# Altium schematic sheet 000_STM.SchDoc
size A; SheetNumber: 2; SheetTotal: 5
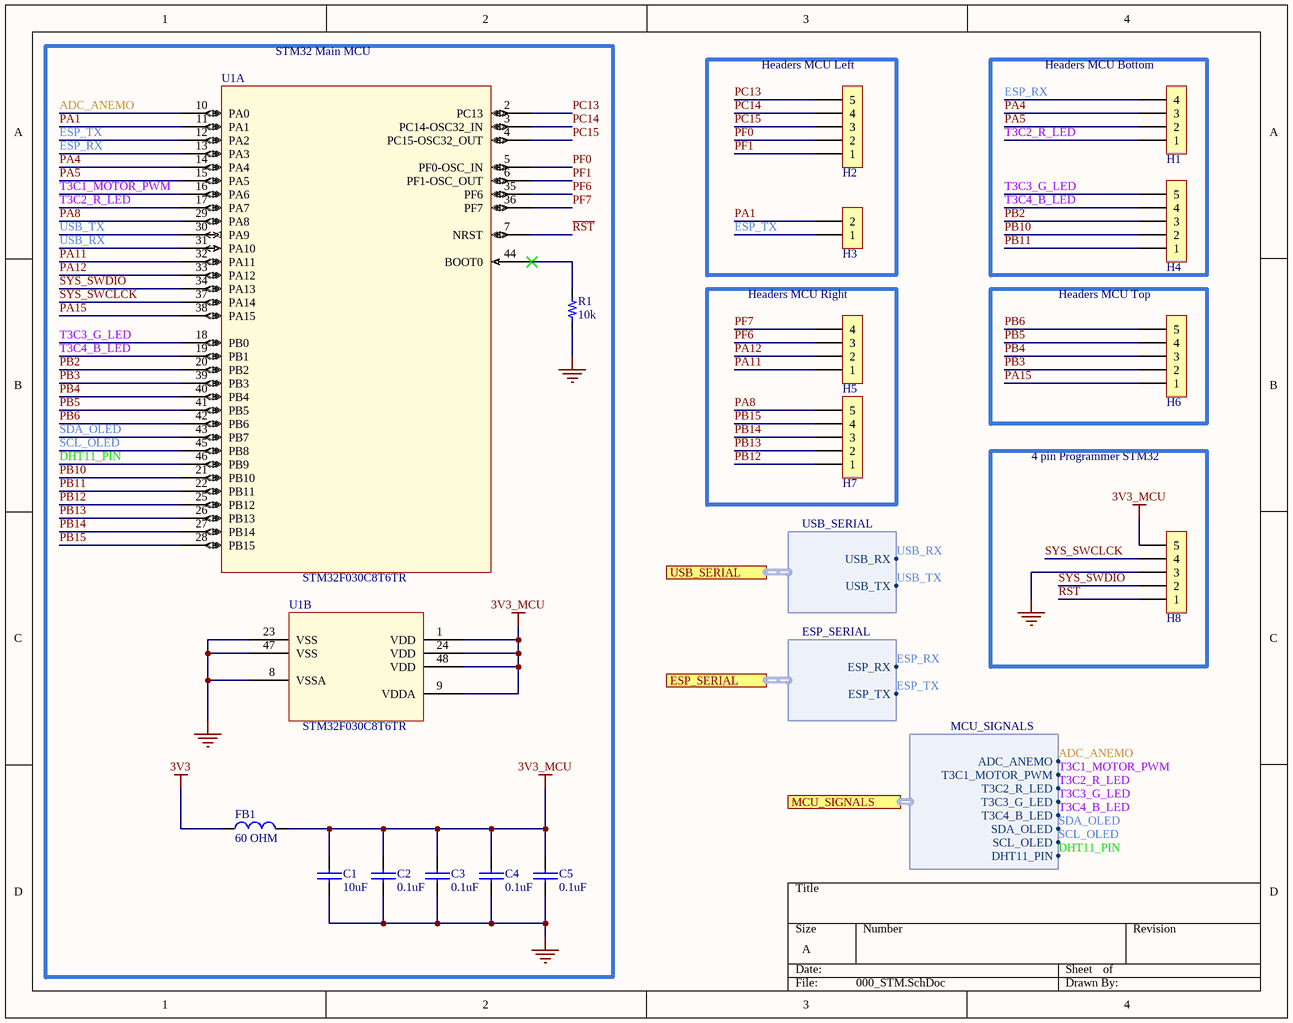
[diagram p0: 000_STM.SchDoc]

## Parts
C1  value 10uF  [0805_cap]  (hidden comment: 10uF 25V)
C2  value 0.1uF  [0603_cap]  (hidden comment: 0.1uF 50V)
C3  value 0.1uF  [0603_cap]  (hidden comment: 0.1uF 50V)
C4  value 0.1uF  [0603_cap]  (hidden comment: 0.1uF 50V)
C5  value 0.1uF  [0603_cap]  (hidden comment: 0.1uF 50V)
FB1  value 60 OHM  [0603_fb]  (hidden comment: 60OHM 2A)
H1  4x1  [H_4x1_TH_2.54mm]  (value not drawn)  (no BOM)
H2  5x1  [H_5x1_TH_100mil]  (value not drawn)  (no BOM)
H3  2x1  [H_2x1_TH_100mil]  (value not drawn)  (no BOM)
H4  5x1  [H_5x1_TH_100mil]  (value not drawn)  (no BOM)
H5  4x1  [H_4x1_TH_2.54mm]  (value not drawn)  (no BOM)
H6  5x1  [H_5x1_TH_100mil]  (value not drawn)  (no BOM)
H7  5x1  [H_5x1_TH_100mil]  (value not drawn)  (no BOM)
H8  5x1  [H_5x1_TH_100mil]  (value not drawn)  (no BOM)
R1  value 10k  [0603_res]  (hidden comment: 10k 1/10W)
U1  STM32F030C8T6TR  [LQFP48_7x7mm]  (parts A,B of 2)

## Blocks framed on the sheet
STM32 Main MCU: C1-C5 FB1 R1 U1
Headers MCU Left: H2 H3
Headers MCU Bottom: H1 H4
Headers MCU Right: H5 H7
Headers MCU Top: H6
4 pin Programmer STM32: H8

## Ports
ESP_SERIAL (harness ESP_SERIAL, see Main[2B], 100_ESP[3A]), MCU_SIGNALS (harness MCU_SIGNALS, see Main[2B], 200_Peripherals_Sensors[1D]), USB_SERIAL (harness USB_SERIAL, see Main[2B], 300_Power[3B])

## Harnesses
MCU_SIGNALS: ADC_ANEMO, T3C1_MOTOR_PWM, T3C2_R_LED, T3C3_G_LED, T3C4_B_LED, SDA_OLED, SCL_OLED, DHT11_PIN
USB_SERIAL: USB_RX, USB_TX
ESP_SERIAL: ESP_RX, ESP_TX

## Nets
3V3: FB1.1
3V3_MCU: C1.1 C2.1 C3.1 C4.1 C5.1 FB1.2 H8.5 U1.1(VDD) U1.9(VDDA) U1.24(VDD) U1.48(VDD)
GND: C1.2 C2.2 C3.2 C4.2 C5.2 H8.3 R1.1 U1.8(VSSA) U1.23(VSS) U1.47(VSS)
ADC_ANEMO: U1.10(PA0) ; port MCU_SIGNALS.ADC_ANEMO
DHT11_PIN: U1.46(PB9) ; port MCU_SIGNALS.DHT11_PIN
ESP_RX: H1.4 U1.13(PA3) ; port ESP_SERIAL.ESP_RX
ESP_TX: H3.1 U1.12(PA2) ; port ESP_SERIAL.ESP_TX
PA1: H3.2 U1.11(PA1)
PA4: H1.3 U1.14(PA4)
PA5: H1.2 U1.15(PA5)
PA8: H7.5 U1.29(PA8)
PA11: H5.1 U1.32(PA11)
PA12: H5.2 U1.33(PA12)
PA15: H6.1 U1.38(PA15)
PB2: H4.3 U1.20(PB2)
PB3: H6.2 U1.39(PB3)
PB4: H6.3 U1.40(PB4)
PB5: H6.4 U1.41(PB5)
PB6: H6.5 U1.42(PB6)
PB10: H4.2 U1.21(PB10)
PB11: H4.1 U1.22(PB11)
PB12: H7.1 U1.25(PB12)
PB13: H7.2 U1.26(PB13)
PB14: H7.3 U1.27(PB14)
PB15: H7.4 U1.28(PB15)
PC13: H2.5 U1.2(PC13)
PC14: H2.4 U1.3(PC14-OSC32_IN)
PC15: H2.3 U1.4(PC15-OSC32_OUT)
PF0: H2.2 U1.5(PF0-OSC_IN)
PF1: H2.1 U1.6(PF1-OSC_OUT)
PF6: H5.3 U1.35(PF6)
PF7: H5.4 U1.36(PF7)
~{RST}: H8.1 U1.7(NRST)
SCL_OLED: U1.45(PB8) ; port MCU_SIGNALS.SCL_OLED
SDA_OLED: U1.43(PB7) ; port MCU_SIGNALS.SDA_OLED
SYS_SWCLCK: H8.4 U1.37(PA14)
SYS_SWDIO: H8.2 U1.34(PA13)
T3C1_MOTOR_PWM: U1.16(PA6) ; port MCU_SIGNALS.T3C1_MOTOR_PWM
T3C2_R_LED: H1.1 U1.17(PA7) ; port MCU_SIGNALS.T3C2_R_LED
T3C3_G_LED: H4.5 U1.18(PB0) ; port MCU_SIGNALS.T3C3_G_LED
T3C4_B_LED: H4.4 U1.19(PB1) ; port MCU_SIGNALS.T3C4_B_LED
USB_RX: U1.31(PA10) ; port USB_SERIAL.USB_RX
USB_TX: U1.30(PA9) ; port USB_SERIAL.USB_TX
NetR1_2: R1.2 U1.44(BOOT0)

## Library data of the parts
C1 = Cap_10uF_0805_25V_: 25V 10uF X5R ±10% 0805 Multilayer Ceramic Capacitors MLCC - SMD/SMT ROHS; Manufacturer: Samsung Electro-Mechanics; Manufacturer Part Number: CL21A106KAYNNNE
C2-C5 = Cap_0.1uF_0603_50V: 50V 100nF Y5V -20%~+80% 0603 Multilayer Ceramic Capacitors MLCC - SMD/SMT ROHS; Manufacturer: Walsin Tech Corp; Manufacturer Part Number: 0603F104Z500CT
FB1 = FB_60_0603_2A: 2A 1 100mΩ 60Ω@100MHz ±25% 0603 Ferrite Beads ROHS; Manufacturer: TAI-TECH; Manufacturer Part Number: HCB1608KF-600T20
H1 H5 = H_Male_4x1_TH_100mil
H2 H4 H6-H8 = H_Male_5x1_TH_100mil
H3 = H_Male_2x1_TH_100mil
R1 = Res_10k_0603_1/10W: RES SMD 10k OHM 5% 1/10W 0603; Manufacturer: FOJAN; Manufacturer Part Number: FRC0603J103TS
U1 = IC_STM32F030C8T6TR_LQFP48_7x7MM: IC MCU 32BIT 64KB FLASH 48LQFP; Manufacturer: STMicroelectronics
